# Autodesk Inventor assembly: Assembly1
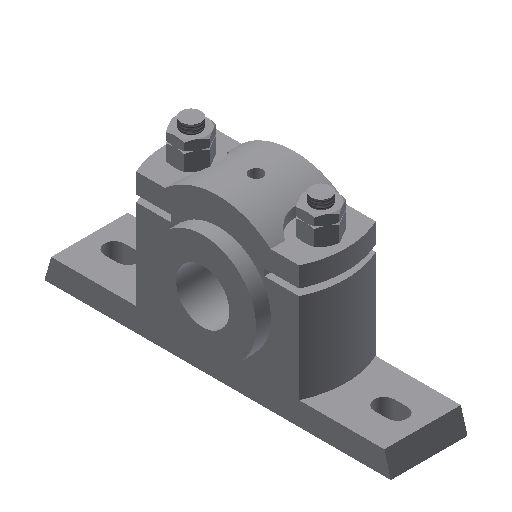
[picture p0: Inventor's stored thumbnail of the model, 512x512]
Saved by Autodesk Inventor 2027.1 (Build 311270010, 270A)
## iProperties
Created: 2015-03
Part Number: Assembly1
Document SubType Name: Assembly
Designer: Sandeep
Author: Sandeep
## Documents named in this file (7)
- E:\Projects 2026\Autodesk Inventor 2027\Resources\Tut_Files\c11_Inv_2027_tut\c11_Inv_2027_tut\c11_Inv_2027_tut\c11_Inv_2027_tut\c11_Inv_tut_2027\c11_tut02_inv\Plummer Block.iam
- E:\Projects 2026\Autodesk Inventor 2027\Resources\Tut_Files\c11_Inv_2027_tut\c11_Inv_2027_tut\c11_Inv_2027_tut\c11_Inv_2027_tut\c11_Inv_tut_2027\c11_tut02_inv\Casting.ipt
- E:\Projects 2026\Autodesk Inventor 2027\Resources\Tut_Files\c11_Inv_2027_tut\c11_Inv_2027_tut\c11_Inv_2027_tut\c11_Inv_2027_tut\c11_Inv_tut_2027\c11_tut02_inv\Brasses.ipt
- E:\Projects 2026\Autodesk Inventor 2027\Resources\Tut_Files\c11_Inv_2027_tut\c11_Inv_2027_tut\c11_Inv_2027_tut\c11_Inv_2027_tut\c11_Inv_tut_2027\c11_tut02_inv\Cap.ipt
- E:\Projects 2026\Autodesk Inventor 2027\Resources\Tut_Files\c11_Inv_2027_tut\c11_Inv_2027_tut\c11_Inv_2027_tut\c11_Inv_2027_tut\c11_Inv_tut_2027\c11_tut02_inv\Bolt.ipt
- E:\Projects 2026\Autodesk Inventor 2027\Resources\Tut_Files\c11_Inv_2027_tut\c11_Inv_2027_tut\c11_Inv_2027_tut\c11_Inv_2027_tut\c11_Inv_tut_2027\c11_tut02_inv\Nut.ipt
- E:\Projects 2026\Autodesk Inventor 2027\Resources\Tut_Files\c11_Inv_2027_tut\c11_Inv_2027_tut\c11_Inv_2027_tut\c11_Inv_2027_tut\c11_Inv_tut_2027\c11_tut02_inv\locknut.ipt
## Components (9 placed, 6 different names)
1. Casting:1 — Mate:1, Mate:2, Insert:1, Insert:2, Angle:1, Angle:2
2. Brasses:1 — Mate:1, Mate:2, Mate:3, Mate:4
3. Cap:1 — Mate:3, Mate:4, Insert:3, Insert:4, Angle:3, Angle:4, Angle:5, Angle:6
4. Bolt:1 — Insert:1, Angle:2
5. Bolt:2 — Insert:2, Angle:1
6. Nut:1 — Insert:3, Insert:5, Angle:3
7. Nut:2 — Insert:4, Insert:6, Angle:6
8. locknut:1 — Insert:5, Angle:4
9. locknut:2 — Insert:6, Angle:5
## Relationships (16: Insert 6, Angle 6, Mate 4)
- Mate:1: Casting:1 ↔ Brasses:1
- Mate:2: Casting:1 ↔ Brasses:1
- Mate:3: Brasses:1 ↔ Cap:1
- Mate:4: Brasses:1 ↔ Cap:1
- Insert:1: Casting:1 ↔ Bolt:1
- Insert:2: Casting:1 ↔ Bolt:2
- Angle:1: Casting:1 ↔ Bolt:2
- Angle:2: Casting:1 ↔ Bolt:1
- Insert:3: Cap:1 ↔ Nut:1
- Insert:4: Cap:1 ↔ Nut:2
- Insert:5: Nut:1 ↔ locknut:1
- Insert:6: Nut:2 ↔ locknut:2
- Angle:3: Cap:1 ↔ Nut:1
- Angle:4: Cap:1 ↔ locknut:1
- Angle:5: Cap:1 ↔ locknut:2
- Angle:6: Cap:1 ↔ Nut:2
